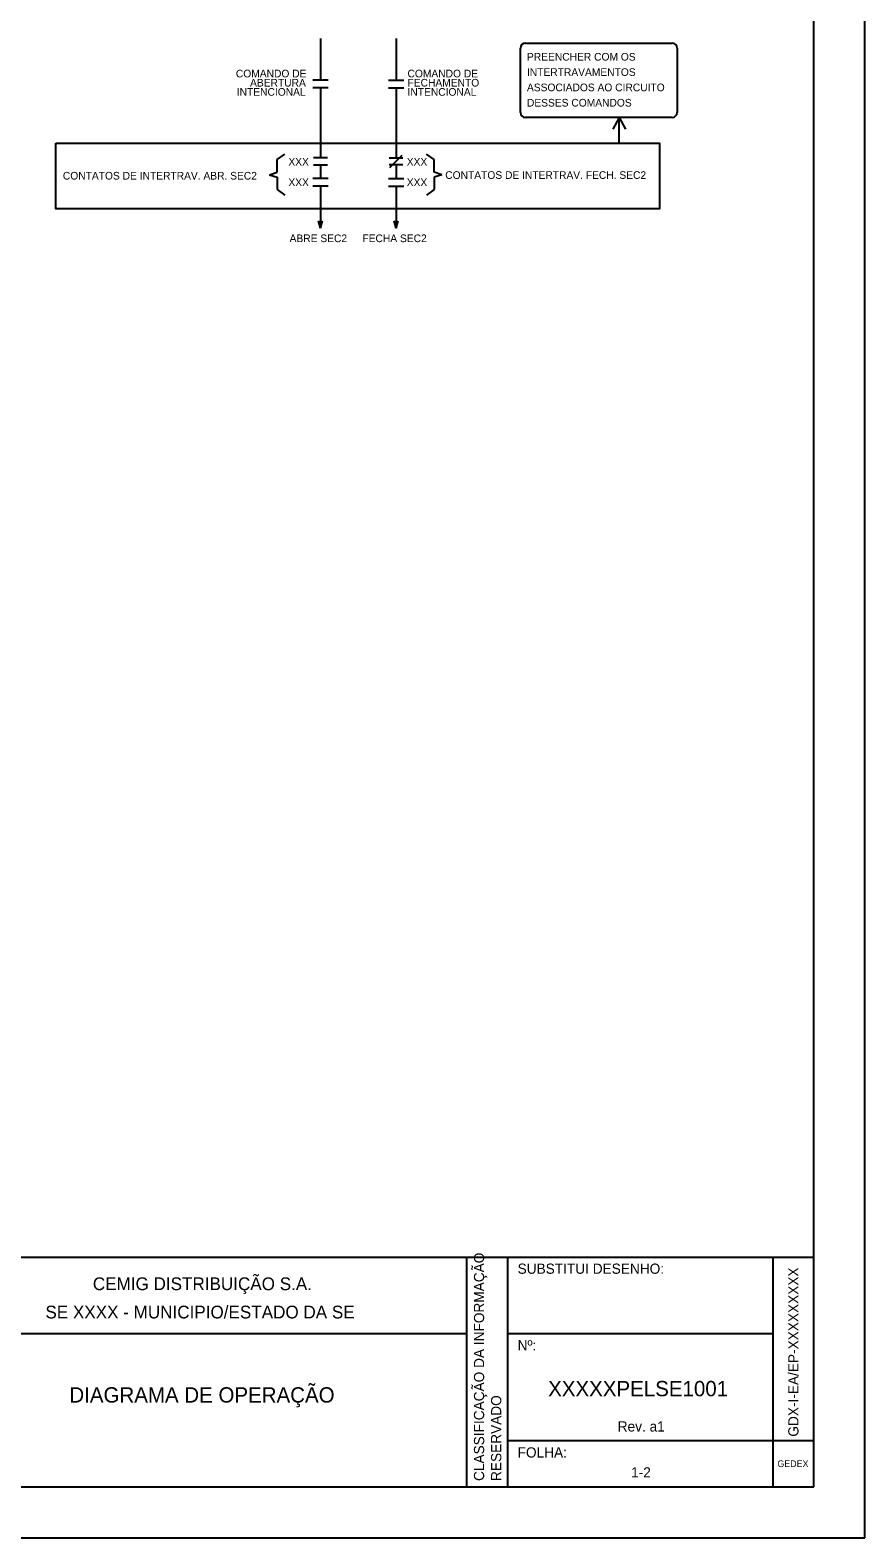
# Model space of a CAD drawing. Extents: x 563 to 1404, y 358 to 952.
# Drawn here: x 1240.1 to 1403.6, y 358 to 653.3 of the extents above; entities that cross this region are included whole.
import ezdxf

# ---------------------------------------------------------------- set-up
doc = ezdxf.new("R2010")
doc.units = 0
doc.layers.add('New Level (0)', color=7, linetype='Continuous')

msp = doc.modelspace()

# ---------------------------------------------------------------- linework, layer by layer
for p, q in [((1296.98, 651.7), (1296.98, 643.53)), ((1311.77, 651.7), (1311.77, 643.53)), ((1298.48, 643.53), (1295.48, 643.53)), ((1298.48, 642.03), (1295.48, 642.03)), ((1296.98, 642.03), (1296.98, 628.29)), ((1310.27, 643.53), (1313.27, 643.53)), ((1310.27, 642.03), (1313.27, 642.03)), ((1311.77, 642.03), (1311.77, 628.29)), ((1288.52, 627.97), (1290.02, 629.06)), ((1288.52, 625.51), (1288.52, 627.97)), ((1298.33, 628.29), (1295.63, 628.29)), ((1295.63, 626.94), (1298.33, 626.94)), ((1296.98, 626.79), (1296.98, 624.28)), ((1310.42, 628.29), (1313.12, 628.29)), ((1313.12, 626.94), (1310.42, 626.94)), ((1310.58, 626.42), (1312.97, 628.81)), ((1311.77, 626.79), (1311.77, 624.28)), ((1319.24, 627.97), (1317.74, 629.06)), ((1319.24, 625.51), (1319.24, 627.97)), ((1287.02, 625.01), (1288.52, 625.51)), ((1287.02, 625.01), (1288.52, 624.51)), ((1288.52, 624.51), (1288.52, 622.11)), ((1298.48, 624.28), (1295.48, 624.28)), ((1310.27, 624.28), (1313.27, 624.28)), ((1320.74, 625.01), (1319.24, 625.51)), ((1320.74, 625.01), (1319.24, 624.51)), ((1319.24, 624.51), (1319.24, 622.11)), ((1288.52, 622.11), (1290.02, 621.02)), ((1298.48, 622.78), (1295.48, 622.78)), ((1296.98, 622.78), (1296.98, 614.55)), ((1310.27, 622.78), (1313.27, 622.78)), ((1311.77, 622.78), (1311.77, 614.55)), ((1319.24, 622.11), (1317.74, 621.02)), ((1296.98, 614.55), (1296.59, 616)), ((1296.98, 614.55), (1297.37, 616)), ((1311.77, 614.55), (1311.38, 616)), ((1311.77, 614.55), (1312.16, 616))]:
    msp.add_line(p, q)
at = {"layer": 'New Level (0)'}
for p, q in [((1403.58, 357.96), (1403.58, 951.96)), ((1403.58, 357.96), (1403.58, 951.96)), ((1393.58, 367.96), (1393.58, 941.96)), ((1393.58, 367.96), (1393.58, 941.96)), ((1337.14, 650.8), (1365.82, 650.8)), ((1336.14, 637.22), (1336.14, 649.8)), ((1366.82, 649.8), (1366.82, 637.22)), ((1365.82, 636.22), (1337.14, 636.22)), ((1355.47, 636.22), (1354.26, 633.92)), ((1355.47, 631.19), (1355.47, 636.22)), ((1355.47, 636.22), (1356.68, 633.92)), ((572.58, 412.96), (1393.58, 412.96)), ((1325.58, 412.96), (1325.58, 367.96)), ((1333.58, 412.96), (1333.58, 367.96)), ((1385.58, 412.96), (1385.58, 367.96)), ((1143.58, 397.96), (1325.58, 397.96)), ((1333.58, 397.96), (1385.58, 397.96)), ((1393.58, 376.96), (1333.58, 376.96)), ((572.58, 367.96), (1393.58, 367.96)), ((572.58, 367.96), (1393.58, 367.96)), ((562.58, 357.96), (1403.58, 357.96)), ((562.58, 357.96), (1403.58, 357.96))]:
    msp.add_line(p, q, dxfattribs=at)
msp.add_lwpolyline([(1245.17, 631.19), (1363.37, 631.19), (1363.37, 618.3), (1245.17, 618.3)], close=True, dxfattribs=at)
for centre, start, end in [((1337.14, 649.8), 90, 180), ((1365.82, 649.8), 0, 90), ((1337.14, 637.22), 180, 270), ((1365.82, 637.22), 270, 0)]:
    msp.add_arc(centre, 1, start, end, dxfattribs=at)

# ---------------------------------------------------------------- texts
for s, p in [('PREENCHER COM OS ', (1337.41, 647.36)), ('COMANDO DE', (1280.41, 644.08)), ('COMANDO DE ', (1314.02, 644.08)), ('INTERTRAVAMENTOS', (1337.41, 644.36)), (' INTENCIONAL', (1280.03, 640.48)), (' ABERTURA', (1282.63, 642.28)), ('FECHAMENTO ', (1314.02, 642.28)), ('INTENCIONAL', (1314.02, 640.48)), ('ASSOCIADOS AO CIRCUITO ', (1337.41, 641.36)), ('DESSES COMANDOS', (1337.41, 638.36)), ('XXX', (1290.69, 626.79)), ('XXX', (1313.87, 626.79)), ('CONTATOS DE INTERTRAV. ABR. SEC2', (1246.53, 624.06)), ('XXX', (1290.69, 622.78)), ('XXX', (1313.87, 622.78)), ('CONTATOS DE INTERTRAV. FECH. SEC2', (1321.41, 624.19)), ('ABRE SEC2', (1290.93, 611.8)), ('FECHA SEC2', (1305.19, 611.8))]:
    msp.add_text(s, height=1.5).set_placement(p)
for s, p in [('CLASSIFICAÇÃO DA INFORMAÇÃO', (1329.03, 369.1)), ('GDX-I-EA/EP-XXXXXXXXX', (1390.58, 377.78)), ('RESERVADO', (1332.38, 369.1))]:
    msp.add_text(s, height=2, rotation=90, dxfattribs=at).set_placement(p)
for s, height, p in [('SUBSTITUI DESENHO:', 2, (1335.58, 409.69)), ('CEMIG DISTRIBUIÇÃO S.A.', 2.5, (1252.4, 406.48)), ('SE XXXX - MUNICIPIO/ESTADO DA SE', 2.5, (1243.11, 400.94)), ('Nº:', 2, (1335.58, 394.69)), ('DIAGRAMA DE OPERAÇÃO', 3, (1247.8, 384.46)), ('XXXXXPELSE1001', 3, (1341.56, 385.69)), ('Rev. a1', 2, (1355.18, 378.78)), ('FOLHA:', 2, (1335.58, 373.69)), ('GEDEX', 1.3, (1386.45, 371.83)), ('1-2', 2, (1357.8, 369.78))]:
    msp.add_text(s, height=height, dxfattribs=at).set_placement(p)

doc.saveas('drawing.dxf')
